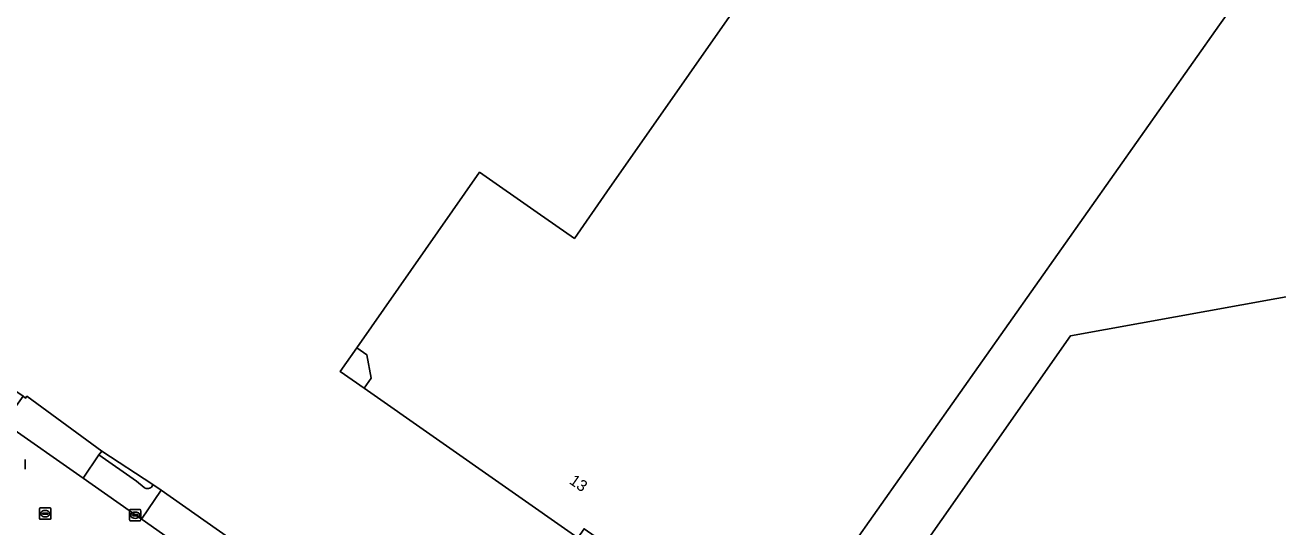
# Model space of a CAD drawing. Extents: x 155018 to 156648, y 383979 to 385733.
# Drawn here: x 155319.4 to 155429.7, y 385103.9 to 385148 of the extents above; entities that cross this region are included whole.
import ezdxf

# ---------------------------------------------------------------- set-up
doc = ezdxf.new("R2010")
doc.units = 0
for name, color, linetype in [('IMGEO_Erf', 7, 'Continuous'), ('IMGEO_Kolk', 7, 'Continuous'), ('IMGEO_Pand', 7, 'Continuous'), ('IMGEO_Pand_nummerreeks', 7, 'Continuous'), ('IMGEO_Pand_overbouw', 7, 'Continuous'), ('IMGEO_Rijbaan_lokaal_gesloten', 7, 'Continuous'), ('IMGEO_Rijbaan_lokaal_open', 7, 'Continuous'), ('IMGEO_Rioolput', 7, 'Continuous'), ('IMGEO_Voetpad_open', 7, 'Continuous')]:
    doc.layers.add(name, color=color, linetype=linetype)

msp = doc.modelspace()

# ---------------------------------------------------------------- linework, layer by layer
at = {"layer": 'IMGEO_Erf'}
msp.add_lwpolyline([(155413.9, 385195.2), (155443.27, 385174.66), (155442.01, 385172.85), (155454.27, 385164.27), (155459.18, 385158.04), (155446.72, 385140.34), (155440.51, 385144.72), (155428.3, 385153.34), (155424.54, 385148.03), (155385.16, 385092.22), (155368.63, 385103.71), (155368.07, 385102.91), (155349.27, 385116.07), (155349.89, 385116.96), (155349.5, 385119.02), (155348.62, 385119.63), (155359.43, 385135.08), (155364.49, 385131.54), (155367.77, 385129.25), (155370.63, 385133.35)], close=True, dxfattribs=at)
for points in [[(155270.84, 385149.33), (155279.45, 385143.26), (155284.56, 385139.65), (155317.35, 385116.7), (155318.53, 385115.87), (155319.24, 385115.37), (155319.46, 385115.21), (155319.58, 385115.36), (155326.19, 385110.55), (155330.68, 385107.6), (155331.41, 385107.09), (155337.34, 385102.95), (155357.01, 385089.19), (155362.77, 385085.18), (155368.94, 385080.86), (155374.5, 385076.98), (155374.69, 385076.84), (155377.55, 385080.91), (155381.07, 385078.44), (155379.97, 385076.65), (155379.05, 385073.83), (155378.3, 385071.51)], [(155411.43, 385120.68), (155432.67, 385124.51), (155438.05, 385132.17), (155467.8, 385111.44), (155471.9, 385108.58), (155466.59, 385100.98), (155474.93, 385095.15), (155457.22, 385069.83), (155453.46, 385069.27), (155453.5, 385068.76)], [(155411.2, 385061.27), (155411.11, 385061.77), (155407.39, 385061.04), (155382.08, 385078.78), (155384.95, 385082.87), (155411.43, 385120.68)]]:
    msp.add_lwpolyline(points, dxfattribs=at)
at = {"layer": 'IMGEO_Kolk'}
for p, q in [((155328.61, 385104.48), (155328.61, 385105.33)), ((155328.69, 385105.4), (155329.54, 385105.4)), ((155329.54, 385104.4), (155328.69, 385104.4)), ((155328.87, 385104.9), (155328.87, 385104.91)), ((155328.91, 385104.95), (155329.31, 385104.95)), ((155329.31, 385104.86), (155328.91, 385104.86)), ((155329.1, 385105.18), (155329.13, 385105.18)), ((155329.12, 385104.62), (155329.1, 385104.62)), ((155329.36, 385104.91), (155329.36, 385104.9)), ((155329.61, 385105.33), (155329.61, 385104.48))]:
    msp.add_line(p, q, dxfattribs=at)
for points in [[(155328.61, 385104.48), (155328.61, 385105.33)], [(155328.69, 385105.4), (155329.54, 385105.4)], [(155329.54, 385104.4), (155328.69, 385104.4)], [(155329.61, 385105.33), (155329.61, 385104.48)]]:
    msp.add_lwpolyline(points, dxfattribs=at)
for centre, radius, start, end in [((155328.69, 385105.33), 0.0765, 91.552, 178.448), ((155328.69, 385105.33), 0.0765, 91.552, 178.448), ((155328.69, 385104.48), 0.0765, 181.552, 268.448), ((155328.69, 385104.48), 0.0765, 181.552, 268.448), ((155328.91, 385104.91), 0.0403, 85.8775, 175.7526), ((155328.91, 385104.9), 0.0366, 178.938, 274.7102), ((155329.32, 385104.91), 0.0386, 1.7309, 96.639), ((155329.31, 385104.9), 0.043, 264.8664, 352.4533), ((155329.54, 385105.33), 0.0765, 1.552, 88.448), ((155329.54, 385105.33), 0.0765, 1.552, 88.448), ((155329.54, 385104.48), 0.0765, 271.552, 358.448), ((155329.54, 385104.48), 0.0765, 271.552, 358.448)]:
    msp.add_arc(centre, radius, start, end, dxfattribs=at)
for centre, major_axis, ratio, start_param, end_param in [((155329.1, 385104.9), (-0.387, 0.002), 0.722429, 4.712389, 7.853982), ((155329.12, 385104.9), (-0.39, 0.002), 0.717154, 1.570796, 4.712389)]:
    msp.add_ellipse(centre, major_axis=major_axis, ratio=ratio, start_param=start_param, end_param=end_param, dxfattribs=at)
at = {"layer": 'IMGEO_Pand'}
msp.add_lwpolyline([(155442.01, 385172.85), (155443.27, 385174.66), (155413.9, 385195.2), (155370.63, 385133.35), (155367.77, 385129.25), (155364.49, 385131.54), (155359.43, 385135.08), (155348.62, 385119.63), (155349.5, 385119.02), (155349.89, 385116.96), (155349.27, 385116.07), (155368.07, 385102.91), (155368.63, 385103.71), (155385.16, 385092.22), (155424.54, 385148.03), (155428.3, 385153.34)], close=True, dxfattribs=at)
msp.add_lwpolyline([(155453.5, 385068.76), (155453.46, 385069.27), (155457.22, 385069.83), (155474.93, 385095.15), (155466.59, 385100.98), (155471.9, 385108.58), (155467.8, 385111.44), (155438.05, 385132.17), (155432.67, 385124.51), (155411.43, 385120.68), (155384.95, 385082.87), (155382.08, 385078.78), (155407.39, 385061.04), (155411.11, 385061.77), (155411.2, 385061.27)], dxfattribs=at)
at = {"layer": 'IMGEO_Pand_overbouw'}
msp.add_lwpolyline([(155349.27, 385116.07), (155349.89, 385116.96), (155349.5, 385119.02), (155348.62, 385119.63), (155347.16, 385117.54)], close=True, dxfattribs=at)
at = {"layer": 'IMGEO_Rijbaan_lokaal_gesloten'}
msp.add_lwpolyline([(155426.08, 385037.13), (155420.14, 385041.29), (155419.86, 385041.58), (155414.44, 385045.35), (155378.61, 385070.28), (155373.16, 385074.07), (155371.07, 385075.54), (155365.02, 385079.79), (155362.62, 385081.43), (155361.07, 385082.55), (155355.21, 385086.68), (155344.84, 385093.91), (155335.61, 385100.39), (155329.74, 385104.51), (155329.67, 385104.56), (155324.53, 385108.17), (155317.59, 385113.03), (155316.9, 385113.52), (155315.7, 385114.36), (155269.21, 385146.94), (155267.26, 385148.3)], dxfattribs=at)
at = {"layer": 'IMGEO_Rijbaan_lokaal_open'}
for points in [[(155319.58, 385115.36), (155319.46, 385115.21), (155319.24, 385115.37), (155317.59, 385113.03), (155324.53, 385108.17), (155325.91, 385110.21), (155326.19, 385110.55)], [(155331.41, 385107.09), (155329.67, 385104.56), (155329.74, 385104.51), (155335.61, 385100.39), (155337.3, 385102.72), (155337.34, 385102.95)]]:
    msp.add_lwpolyline(points, close=True, dxfattribs=at)
at = {"layer": 'IMGEO_Rioolput'}
for p, q in [((155319.42, 385109.81), (155319.42, 385108.96)), ((155320.69, 385104.61), (155320.69, 385105.47)), ((155320.76, 385105.54), (155321.62, 385105.54)), ((155321.69, 385105.47), (155321.69, 385104.61)), ((155321.62, 385104.54), (155320.76, 385104.54)), ((155320.95, 385105.03), (155320.95, 385105.05)), ((155320.99, 385105.08), (155321.39, 385105.08)), ((155321.39, 385105), (155320.99, 385105)), ((155321.2, 385104.76), (155321.17, 385104.76)), ((155321.18, 385105.32), (155321.2, 385105.32)), ((155321.43, 385105.05), (155321.43, 385105.03))]:
    msp.add_line(p, q, dxfattribs=at)
for points in [[(155319.42, 385109.81), (155319.42, 385108.96)], [(155320.69, 385104.61), (155320.69, 385105.47)], [(155320.76, 385105.54), (155321.62, 385105.54)], [(155321.69, 385105.47), (155321.69, 385104.61)], [(155321.62, 385104.54), (155320.76, 385104.54)]]:
    msp.add_lwpolyline(points, dxfattribs=at)
for centre, radius, start, end in [((155320.77, 385105.46), 0.0765, 91.552, 178.448), ((155320.77, 385105.46), 0.0765, 91.552, 178.448), ((155321.61, 385105.46), 0.0765, 1.552, 88.448), ((155321.61, 385105.46), 0.0765, 1.552, 88.448), ((155320.77, 385104.62), 0.0765, 181.552, 268.448), ((155320.77, 385104.62), 0.0765, 181.552, 268.448), ((155320.99, 385105.04), 0.0403, 85.8775, 175.7526), ((155320.98, 385105.03), 0.0366, 178.938, 274.7102), ((155321.39, 385105.04), 0.0386, 1.7309, 96.639), ((155321.39, 385105.04), 0.043, 264.8664, 352.4533), ((155321.61, 385104.62), 0.0765, 271.552, 358.448), ((155321.61, 385104.62), 0.0765, 271.552, 358.448)]:
    msp.add_arc(centre, radius, start, end, dxfattribs=at)
for centre, major_axis, ratio, start_param, end_param in [((155321.18, 385105.04), (-0.387, 0.002), 0.722429, 4.712389, 7.853982), ((155321.2, 385105.04), (-0.39, 0.002), 0.717154, 1.570796, 4.712389)]:
    msp.add_ellipse(centre, major_axis=major_axis, ratio=ratio, start_param=start_param, end_param=end_param, dxfattribs=at)
at = {"layer": 'IMGEO_Voetpad_open'}
for points in [[(155329.23, 385107.89), (155325.91, 385110.21), (155324.53, 385108.17), (155329.67, 385104.56), (155331.41, 385107.09), (155330.68, 385107.6), (155330.61, 385107.46)], [(155326.19, 385110.55), (155325.91, 385110.21), (155329.23, 385107.89), (155329.91, 385107.35)], [(155330.61, 385107.46), (155330.68, 385107.6), (155326.19, 385110.55)], [(155329.91, 385107.35), (155329.23, 385107.89)]]:
    msp.add_lwpolyline(points, dxfattribs=at)
msp.add_arc((155330.21, 385107.71), 0.472, 230.7571, 328.0878, dxfattribs=at)
msp.add_arc((155330.21, 385107.71), 0.472, 230.7571, 328.0878, dxfattribs=at)

# ---------------------------------------------------------------- texts
at = {"layer": 'IMGEO_Pand_nummerreeks'}
msp.add_text('13', height=1, rotation=325.1817, dxfattribs=at).set_placement((155367.25, 385107.74))

doc.saveas('drawing.dxf')
